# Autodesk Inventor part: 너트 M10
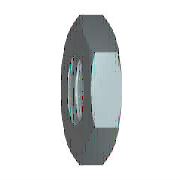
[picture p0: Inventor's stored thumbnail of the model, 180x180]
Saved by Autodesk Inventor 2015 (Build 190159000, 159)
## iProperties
IsCustomPart: 1
Created: 2012-02
Part Number: 너트 M10
Material: 스테인리스강
Description: 미터법 정밀 피치 스레드가 있는 6각 가는 너트(모따기됨)
Document SubType Name: Modeling
Standard: ISO 8675
Designer: mduedu
Standard Revision: Second edition 1999-08-15
Standards Organization: ISO
Language: ko-KR
Size Designation: M10 x 1
Categories: <MemberInstance><Categories><Category DisplayName="조임쇠" InternalName="e4da775c-781d-43d5-af7c-5136215cf5a6" Mnemonic="FSTN"><Category DisplayName="너트" InternalN
Density: 8.08 g/cm^3
Appearance: 기본값
Author: mduedu
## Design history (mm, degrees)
sketch "스케치1"
  geometry: L1 (-9.238, 0)-(-4.619, 8); L2 (-4.619, 8)-(4.619, 8); L3 (4.619, 8)-(9.238, 0); L4 (9.238, 0)-(4.619, -8); L5 (4.619, -8)-(-4.619, -8); L6 (-4.619, -8)-(-9.238, 0); 2 further points
  constraints: 12 end point, 1 coincident, 1 horizontal, 11 other
  dimensions: "d0" = 18.47521 distance of L3.end L1.start (= 1.1547 x SW)
extrude "본체" new body sketch "스케치1" distance "d1" = 5 (= KOH); taper "d2" = 0 deg
sketch "스케치2"
  geometry: L1 (0, 4.619)-(0, 9.238) reference; L2 (0, 9.238)-(5, 9.238) reference; L3 (5, 4.619)-(5, 9.238) reference; L4 (-1, 0)-(6, 0) reference; L5 (1.11, 9.238)-(0, 7.315); L6 (3.89, 9.238)-(5, 7.315)
  constraints: 4 end point, 4 point on line
  dimensions: "d3" = 30 deg angle of L1 L5 (= ANG1); "d4" = 30 deg angle of L3 L6 (= ANG2); "d5" = 14.63 diameter of L5.end L4 (= SW0); "d6" = 14.63 diameter of L6.end L4 (= SW01)
revolve "모따기1" sketch "스케치2" stored, may be unused: angle "d7" = 90 deg
sketch "스케치3"
  geometry: 4 further points
  constraints: 1 coincident, 1 other
hole "스레드" sketch "스케치3" at (0, 0) diameter "d25" = 8.91747; stored, may be unused: countersink angle "d29" = 82 deg, drill point angle "d31" = 118 deg; dims "d26" = 6, "d27" = 4, "d28" = 2, "d30" = 8
workaxis "Work Axis1"
workplane "Work Plane1"
body "Solid1"
chamfer "모따기2" distance "d8" = 0.54127 (= -0.5 x GD1 + 0.5 x NND); stored, may be unused: angle "d9" = 30 deg, second distance "d40" = 0.54127 (= -0.5 x GD1 + 0.5 x NND)
chamfer "모따기3" distance "d10" = 0.54127 (= -0.5 x GD1 + 0.5 x NND); stored, may be unused: angle "d11" = 30 deg, second distance "d41" = 0.54127 (= -0.5 x GD1 + 0.5 x NND)
other parameters: "ANG1" = 30 deg [user parameter; used in 1 equation term], "ANG2" = 30 deg [user parameter; used in 1 equation term], "KOH" = 5 [user parameter; used in 1 equation term], "SW" = 16 [user parameter; used in 1 equation term], "SW0" = 14.63 [user parameter; used in 2 equation terms], "SW01" = 14.63 (= SW0) [user parameter; used in 1 equation term], "GD1" = 8.91747 (computed from THREADDIA, PTC, TOA) [user parameter; used in 4 equation terms], "d13" = 0, "d14" = 0, "d39" = 0, "d42" = 0, "GUL" = 0.54127 (= 0.541266 x PTC) [user parameter], "TOA" = 30 deg [user parameter; used in 1 equation term], "PTC" = 1 [user parameter; used in 4 equation terms], "E0" = 17.77 [user parameter], "GAL" = 0.54127 (= 0.541266 x PTC) [user parameter]
